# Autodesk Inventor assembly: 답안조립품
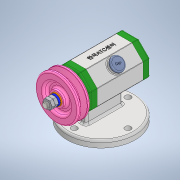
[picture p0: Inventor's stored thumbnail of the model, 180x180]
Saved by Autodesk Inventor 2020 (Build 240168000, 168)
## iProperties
Created: 2021-02
Part Number: 답안조립품
Document SubType Name: Assembly
Designer: USER
Author: USER
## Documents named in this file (14)
- C:\Users\USER\Desktop\710204V1021\답안조립품.iam
- C:\Users\USER\Desktop\710204V1021\본체.ipt
- C:\Users\USER\Desktop\710204V1021\뒤커버.ipt
- C:\Users\USER\Desktop\710204V1021\베어링 15 x 32 x 9.ipt
- C:\Users\USER\Desktop\710204V1021\축.ipt
- C:\Users\USER\Desktop\710204V1021\앞커버.ipt
- C:\Users\USER\Desktop\710204V1021\오일 실 15 25 7.ipt
- C:\Users\USER\Desktop\710204V1021\키 3 x 3 x 12.ipt
- C:\Users\USER\Desktop\710204V1021\V벨트풀리.ipt
- C:\Users\USER\Desktop\710204V1021\와셔 8x17.ipt
- C:\Users\USER\Desktop\710204V1021\스프링와셔 8.ipt
- C:\Users\USER\Desktop\710204V1021\너트 M8.ipt
- C:\Users\USER\Desktop\710204V1021\볼트 M4 x 12.ipt
- C:\Users\USER\Desktop\710204V1021\고무캡.ipt
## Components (2 placed, 2 different names)
1. V벨트풀리:1
2. 고무캡:1
